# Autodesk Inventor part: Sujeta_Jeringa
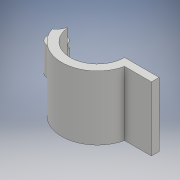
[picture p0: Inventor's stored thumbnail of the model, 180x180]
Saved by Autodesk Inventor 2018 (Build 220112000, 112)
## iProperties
Part Number: Sujeta_Jeringa
Material: Genérico
Document SubType Name: Modeling
Designer: ULISES
Density: 1 g/cm^3
Appearance: Valor por defecto
Author: ULISES
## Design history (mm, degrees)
sketch "Boceto1"
  geometry: L1 (10.9, 0)-(24, 0); L2 (24, 0)-(24, -3); L3 (24, -3)-(13.572, -3); L4 (-10.9, 0)-(-19.4, 0); L5 (-19.4, 0)-(-19.4, 3.5); L6 (-19.4, 3.5)-(-10.9, 3.5); L7 (-10.9, 3.5)-(-10.9, 0); L8 (-10.9, 0)-(-19.4, 0); L9 (-19.4, 0)-(-19.4, -3.5); L10 (-19.4, -3.5)-(-10.9, -3.5); L11 (-10.9, -3.5)-(-10.9, 0); A1 r 10.9 centre (0, 0) between (-10.9, 0) and (10.9, 0); A2 r 13.9 centre (0, 0) between (-13.9, 0) and (13.572, -3); 1 further point
  constraints: 22 end point, 5 parallel, 4 point on circle, 3 horizontal, 3 perpendicular, 2 centre point, 1 coincident, 1 horizontal alignment, 1 point on line, 1 tangent
  dimensions: "d0" = 21.8 diameter of A1; "d1" = 3 radial gap between concentric circles of A1 A2; "d4" = 3.5 distance of L4.end L5.end; "d5" = 8.5 distance of L5.end L6.end; "d6" = 3.5 distance of L8.end L9.end; "d7" = 8.5 distance of L9.end L10.end (= d5); "d39" = 13.1 distance from line of L1.start L2; "d40" = 3 distance of L1.end L2.end
extrude "Extrusión1" new body sketch "Boceto1" distance "d8" = 25; taper "d9" = 0 deg
fillet "Empalme1" dims "d15" = 3.5
sketch "Boceto3"
  geometry: L1 (-19.4, -3.5)-(-13.452, -3.5) reference; L2 (13.572, -3)-(24, -3) reference; L3 (24, -3)-(24, 0) reference; L4 (24, 0)-(10.9, 0) reference; L5 (-10.9, 0)-(-10.9, 3.5) reference; L6 (-19.4, 0)-(-19.4, -3.5) reference; L7 (-10.9, 3.5)-(-15.9, 3.5) reference; C1 r 1.7 at (-15.9, 0); A1 r 3.5 centre (-15.9, 0) between (-15.9, 3.5) and (-19.4, 0) reference; A2 r 13.9 centre (0, 0) between (-13.452, -3.5) and (13.572, -3) reference; A3 r 10.9 centre (0, 0) between (-10.9, 0) and (10.9, 0) reference; 1 further point
  constraints: 1 centre point, 1 coincident
  dimensions: "d16" = 3.4 diameter of C1
extrude "Extrusión3" cut sketch "Boceto3" distance "d17" = 35; taper "d18" = 0 deg
sketch "Boceto5"
  geometry: L1 (-10.9, 0)-(-10.9, 3.5) reference; L2 (-10.9, 3.5)-(-15.9, 3.5) reference; L3 (-10.9, 3.5)-(-12.4, 3.5); L4 (-12.4, 3.5)-(-12.4, 0); L5 (-12.4, 0)-(-10.9, 0); L6 (-10.9, 0)-(-10.9, 3.5); 1 further point
  constraints: 8 end point, 2 parallel, 1 horizontal, 1 perpendicular
  dimensions: "d20" = 1.5 distance between parallel lines of L1 L4; "d21" = 3.5 distance between parallel lines of L2 L5
extrude "Extrusión4" cut sketch "Boceto5" distance "d22" = 500; taper "d23" = 0 deg
fillet "Empalme2" dims "d24" = 3.5
sketch "Boceto6"
  geometry: C1 r 1.7 at (15.9, 0) reference; C2 r 5.25 at (15.9, 0); 1 further point
  constraints: 1 centre point, 1 coincident
  dimensions: "d29" = 10.5 diameter of C2
extrude "Extrusión5" cut sketch "Boceto6" distance "d27" = 6.5; taper "d28" = 0 deg
sketch "Boceto7"
  geometry: C1 r 1.7 at (-15.9, 0) reference; C2 r 5.25 at (-15.9, 0); 1 further point
  constraints: 1 centre point, 1 coincident
  dimensions: "d30" = 10.5 diameter of C2
extrude "Extrusión6" cut sketch "Boceto7" distance "d31" = 7.5; taper "d32" = 0 deg
sketch "Boceto8"
  geometry: L1 (10.517, -1.323)-(10.819, -1.323); L2 (-10.6, 0)-(-10.9, 0); A1 r 10.9 centre (0, 0) between (-10.9, 0) and (10.819, -1.323) reference; A2 r 10.6 centre (0, 0) between (-10.6, 0) and (10.517, -1.323); 1 further point
  constraints: 4 end point, 2 point on circle, 1 centre point, 1 parallel
  dimensions: "d33" = 0.3 radial gap between concentric circles of A1 A2
extrude "Extrusión7" join sketch "Boceto8" distance "d34" = 25; taper "d35" = 0 deg
chamfer "Chaflán1" distance "d36" = 0.3; stored, may be unused: second distance "d37" = 2, angle "d38" = 45 deg
node "Sólido1"
node "Contorno proyectado1"
other parameters: "d12" = 7
